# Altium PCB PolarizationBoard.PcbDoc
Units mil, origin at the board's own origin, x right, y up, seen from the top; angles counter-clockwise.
Board outline 2690 x 2935 mil, 2 copper layers (Top Layer, Bottom Layer); 18 components, 12 nets, 69 pads, 11 vias.
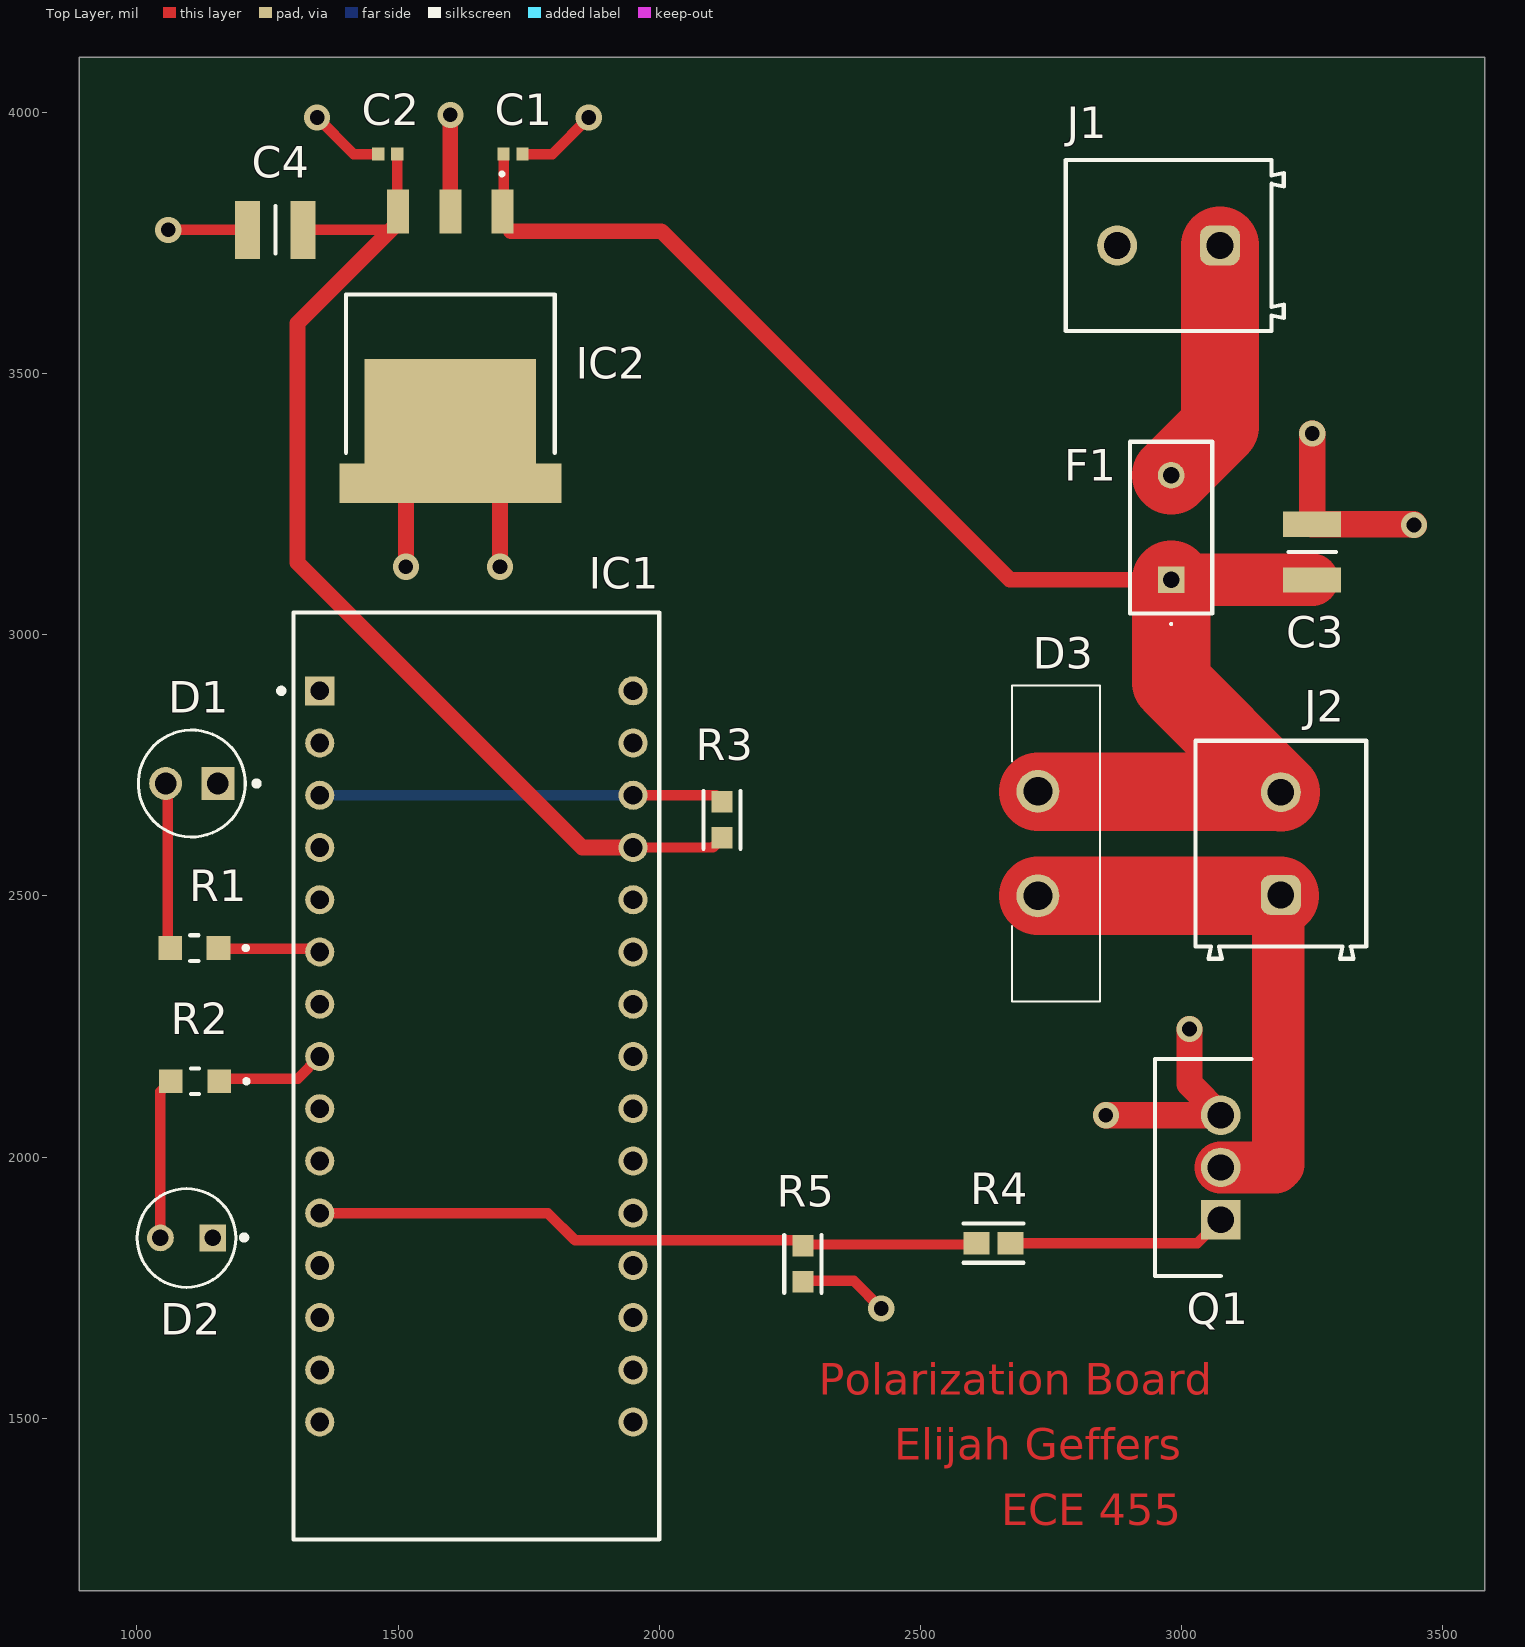
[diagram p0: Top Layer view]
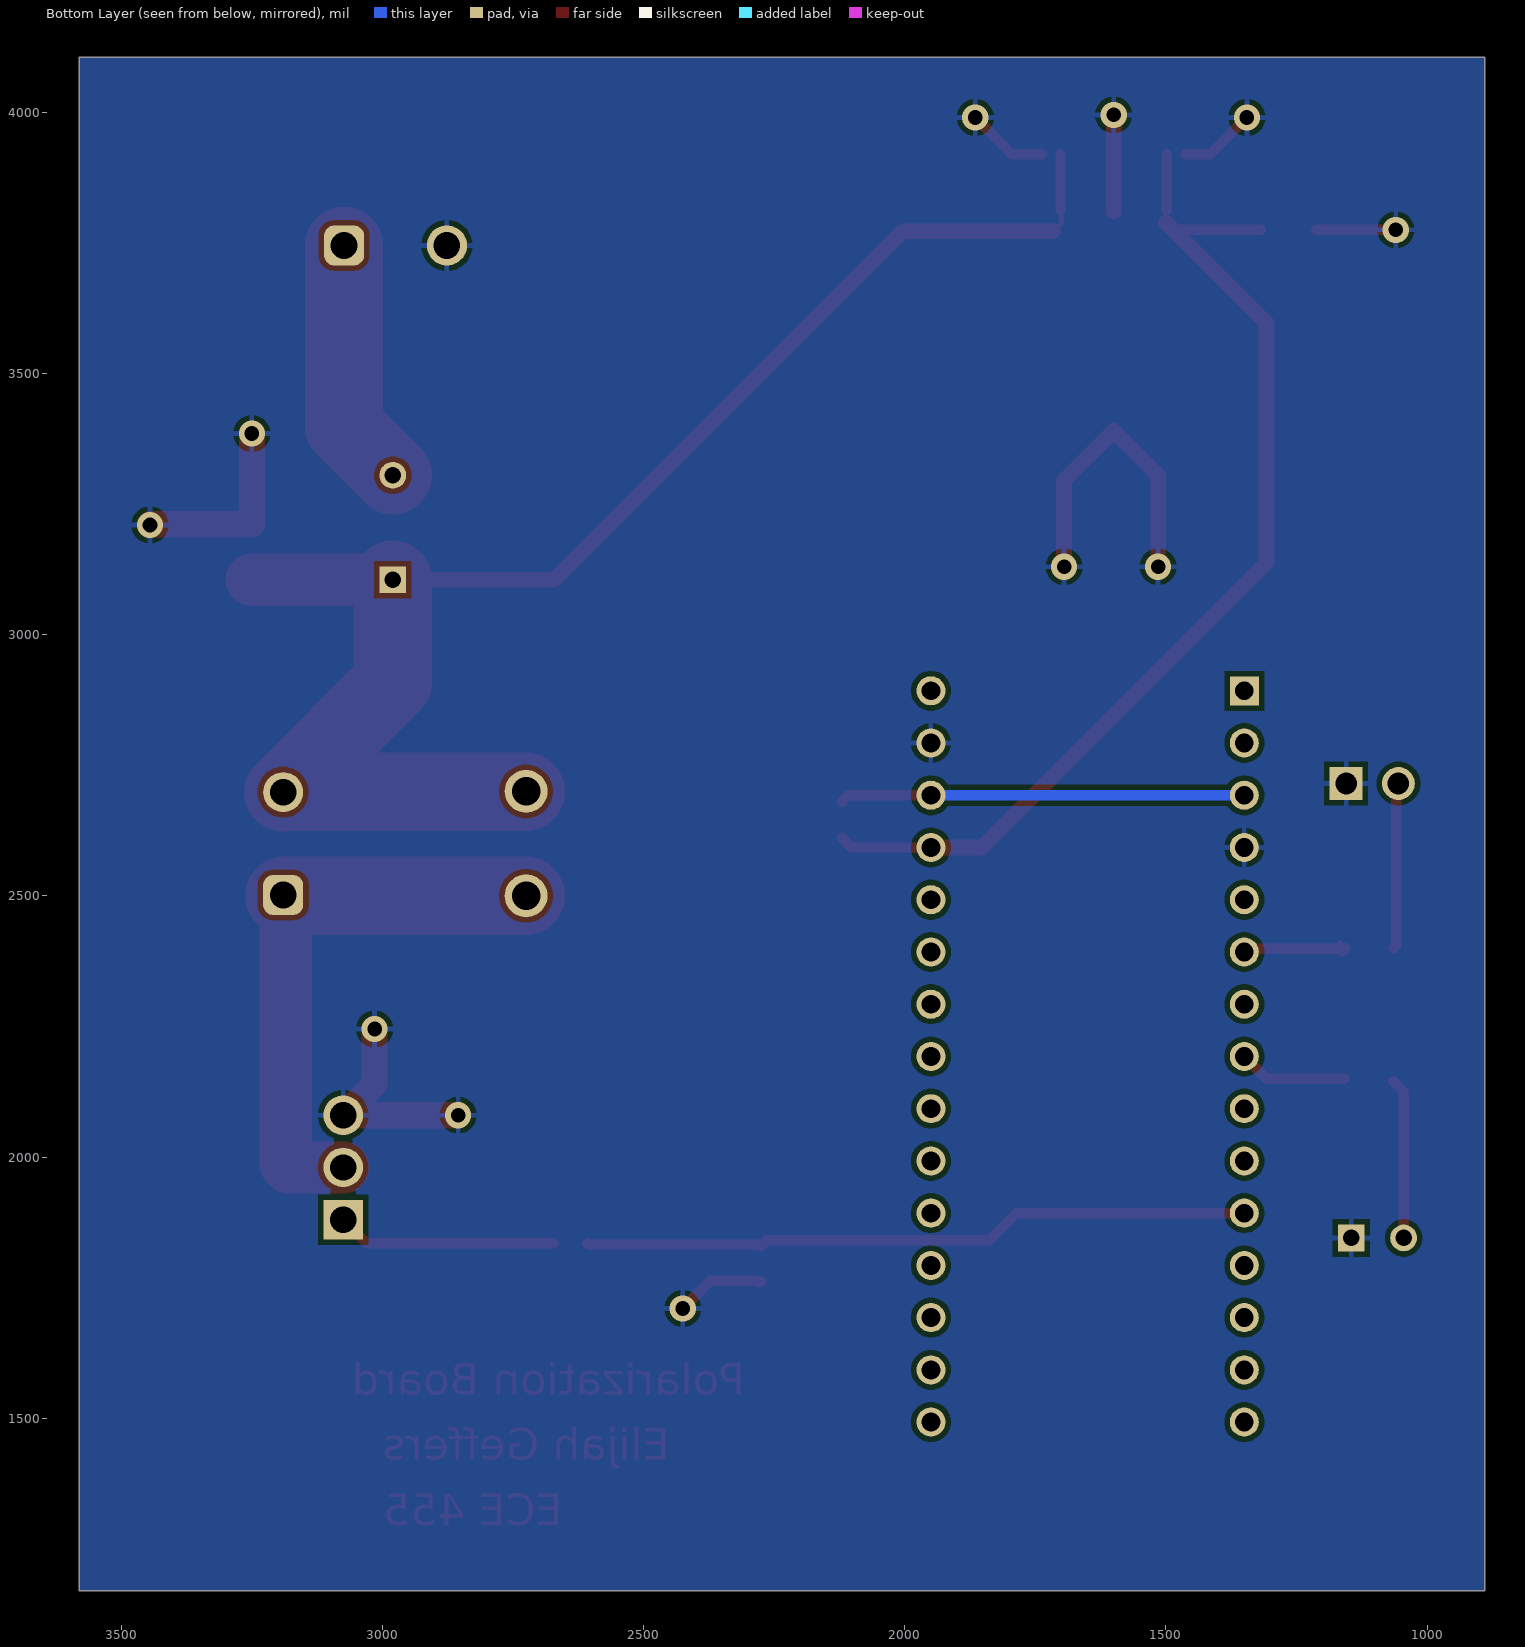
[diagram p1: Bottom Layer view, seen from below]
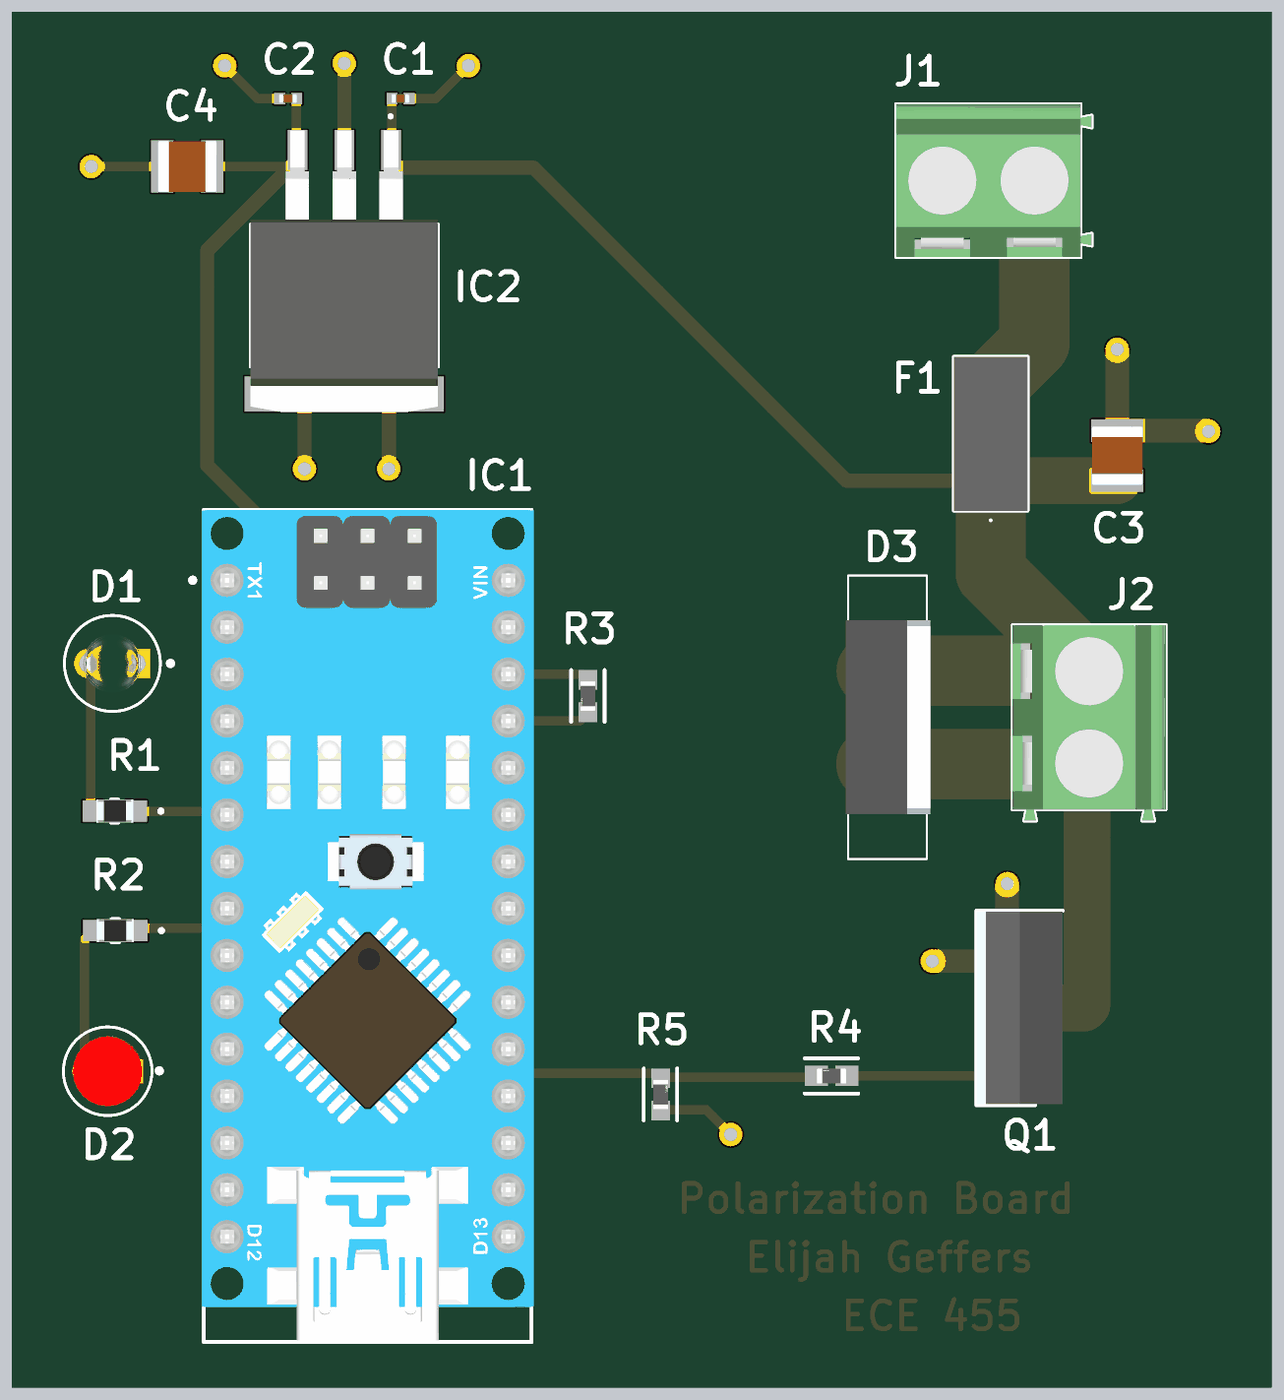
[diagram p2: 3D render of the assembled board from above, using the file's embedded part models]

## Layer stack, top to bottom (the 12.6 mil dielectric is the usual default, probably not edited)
Top Solder: solder mask 0.4, Solder Resist, Dk 3.5
Top Layer: signal copper 1.4
Dielectric 1: dielectric 12.6, FR-4, Dk 4.8
Bottom Layer: signal copper 1.4
Bottom Solder: solder mask 0.4, Solder Resist, Dk 3.5

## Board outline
890,1170 890,4105 3580,4105 3580,1170

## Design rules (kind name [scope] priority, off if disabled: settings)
Clearance [All] p1: gap=10 ignorepadtopadclearanceinfootprint=FALSE
Height [All] p1: minheight=0 maxheight=2000 prefheight=500
PolygonConnect [All] p1: connectstyle=Relief reliefconductorwidth=10 reliefentries=4 polygonreliefangle="90 Angle" airgapwidth=10
RoutingVias [All] p1: holewidth=28 width=50 viastyle="Through Hole" minholewidth=28 minwidth=50 maxholewidth=28 maxwidth=50
SolderMaskExpansion [All] p1: expansion=4 istentingtop=FALSE
SupplyNets "Schematic Supply Nets" [InNet('GND')] p1: voltage=0.000
Width [All] p1: maxlimit=300 minlimit=10 preferedwidth=10 bottomlayer_maxwidth=50 minimp=50.000000 maximp=50.000000 favimp=50.000000
29 further rules are at their usual default settings.

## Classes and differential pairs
component class PolarizationBoard: C1 C2 C3 C4 D1 D2 D3 F1 IC1 IC2 J1 J2 Q1 R1 R2 R3 R5

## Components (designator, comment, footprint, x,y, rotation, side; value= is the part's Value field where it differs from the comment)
C1 "0.22uF" CAPC1005X55N 1720,3920 r0 top
C2 "0.1uF" CAPC1005X55N 1480,3920 r180 top
C3 "10uF" CAPC3225X280N 3250,3158.15 r90 top
C4 "10uF" CAPC3225X280N 1265,3775 r0 top
D1 "LED" FP-6_544-5255_01-4-MFG 1105,2715 r180 top
D2 "LED" FP-LTL-1CHEE-MFG 1095,1845 r180 top
D3 "MBR1045" MBR1045 2712.8,2600 r270 top
F1 "15A" 0697H915002 2980,3105 r90 top
IC1 "A000005" FP-A000005-MFG 1650,2155 r0 top
IC2 "LM7805SX/NOPB" KTT0003B 1600,3311.26 r90 top
J1 "+12V" 691213710002 2975,3745 r180 top
J2 "SENSOR COIL" 691213710002 3190,2600 r90 top
Q1 "IRLZ44NPBF" TO254P469X1042X1967-3P 3075,1880 r90 top
R1 "1.5k" ERA6AEB101V 1110,2400 r180 top
R2 "1.5k" ERA6AEB101V 1111.26,2145 r180 top
R3 "10k" FP-AC0603-IPC_A 2120,2645.48 r270 top
R4 "150" FP-RG1608-IPC_A 2640,1835 r180 top
R5 "10k" FP-AC0603-IPC_A 2275,1795.48 r90 top

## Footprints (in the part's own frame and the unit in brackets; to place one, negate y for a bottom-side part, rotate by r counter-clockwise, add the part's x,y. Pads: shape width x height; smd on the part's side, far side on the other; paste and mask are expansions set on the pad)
0697H915002 [mm]
  rect 1.3x1.3 hole 0.8: 1(0,0)
  round 1.3 hole 0.8: 2(5.08,0)
  silkscreen extent -2.2,-2 6.72,2, body extent -1.64,-2 6.72,2, height 8.2
691213710002 [mm] "5,00mm - modular - green - Horizontal entry with rising cage clamp -  10,0mm height - 02p"
  rrect50% 1.95x1.95 hole 1.3: 1(-2.5,0)
  round 1.95 hole 1.3: 2(2.5,0)
  silkscreen extent -5.6,-4.15 5,4.15, body extent -5.6,-4.15 5,4.15, height 10.05
CAPC1005X55N [mm]
  rect 0.6x0.62 smd: 1(-0.46,0) 2(0.46,0)
  body extent -0.5,-0.25 0.5,0.25, height 0.55
CAPC3225X280N [mm]
  rect 1.22x2.82 smd: 1(-1.35,0) 2(1.35,0)
  silkscreen extent 0,-1.15 0,1.15, body extent -1.6,-1.4 1.6,1.4, height 2.5
ERA6AEB101V [mm]
  rect 1.15x1.15 smd: 1(-1.175,0) 2(1.175,0)
  silkscreen extent -2.6,-0.63 0.2,0.63, body extent -1,-0.63 1,0.63, height 0.5
FP-6_544-5255_01-4-MFG [mm]
  rect 1.6x1.6 hole 1.05 paste-2539.97 mask+0: 1(-1.27,0)
  round 1.6 hole 1.05 paste-2539.97 mask+0: 2(1.27,0)
  silkscreen extent -3.27,-2.6 2.6,2.6, body extent -2.32,-2.32 2.32,2.32, height 0.25
FP-A000005-MFG [mil]
  rect 55.67x55.67 hole 35.98 paste-99999 mask+0: 1(-300,737.5)
  round 55.67 hole 35.98 paste-99999 mask+0: 2(-300,637.5) 3(-300,537.5) 4(-300,437.5) 5(-300,337.5) 6(-300,237.5) 7(-300,137.5) 8(-300,37.5) 9(-300,-62.5) 10(-300,-162.5) 11(-300,-262.5) 12(-300,-362.5) 13(-300,-462.5) 14(-300,-562.5) 15(-300,-662.5) 16(300,-662.5) 17(300,-562.5) 18(300,-462.5) 19(300,-362.5) 20(300,-262.5) 21(300,-162.5) 22(300,-62.5) 23(300,37.5) 24(300,137.5) 25(300,237.5) 26(300,337.5) 27(300,437.5) 28(300,537.5) 29(300,637.5) 30(300,737.5)
  silkscreen extent -379,-888 350,888, body extent -354,-891 354,891, height 10
FP-AC0603-IPC_A [mil]
  rect 41.68x39.85 smd paste+0 mask+0: 1(-34.52,0) 2(34.52,0)
  silkscreen extent -55,-36 55,36, body extent -75,-40 75,40, height 10
FP-LTL-1CHEE-MFG [mm]
  rect 1.3x1.3 hole 0.8 paste-2539.97 mask+0: 1(-1.27,0)
  round 1.3 hole 0.8 paste-2539.97 mask+0: 2(1.27,0)
  silkscreen extent -2.93,-2.4 2.4,2.4, body extent -2.15,-2.15 2.15,2.15, height 0.25
FP-RG1608-IPC_A [mil]
  rect 49.41x43.55 smd paste+0 mask+0: 1(-32.51,0) 2(32.51,0)
  silkscreen extent -57,-38 57,38, body extent -77,-41 77,41, height 10
KTT0003B [mm]
  rect 2.16x1.07 smd: 1(12.67,-2.54) 2(12.67,0) 3(12.67,2.54)
  rect 7x8.33 smd: 4(2,0)
  rect 1.91x1.235 smd: 5(-0.545,4.782) 6(-0.545,-4.782)
  silkscreen extent 0.94,-5.08 14.56,5.08, body extent -1.52,-5.08 13.72,5.08, height 4.54
MBR1045 [mm]
  round 2.085 hole 1.39: 1(-2.54,0.31) 2(2.54,0.31)
  silkscreen extent -7.68,-0.95 7.68,3.32, body extent -5.25,-1.07 5.25,3.52, height 28.86
TO254P469X1042X1967-3P [mm]
  rect 1.92x1.92 hole 1.28: 1(0,0)
  round 1.92 hole 1.28: 2(2.54,0) 3(5.08,0)
  silkscreen extent -2.73,-1.5 7.81,3.19, body extent -2.67,-1.5 7.75,3.19, height 18.84

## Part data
C1: library part MLASU105SB5224KFNA01, "MLASU105SB5224KFNA01", Manufacturer_Name="TAIYO YUDEN"
C2: library part MCASU105SB5104MFNA01, "MCASU105SB5104MFNA01", Manufacturer_Name="TAIYO YUDEN"
C3 C4: library part MCASU32MAB7106KPNA1J, "MCASU32MAB7106KPNA1J", Manufacturer_Name="TAIYO YUDEN", Mouser Part Number=963-U32MAB7106KPNA1J
D1: library part CMP-00030-55433990-1, "TLLG4400 (G)", Case/Package=T, Color=Green, Forward Current=2mA, Forward Voltage=1.9V, Max Operating Temperature=100°C, Max Power Dissipation=20mW, Min Operating Temperature=-40°C, Reverse Voltage=20V, Voltage Rating (DC)=2.4V
D2: library part CMP-22017-000040-1, "LTL-1CHEE (R)", Case/Package=T, Color=Red, Forward Current=30mA, Forward Voltage=2V, Max Operating Temperature=100°C, Max Power Dissipation=100mW, Min Operating Temperature=-55°C, Package Quantity=1000, Reverse Voltage=5V, Test Current=10mA
D3: "Schottky Diode", Manufacturer_Name=onsemi, Mouser Part Number=512-MBR1045
F1: library part 0697H9150-02, "0697H9150-02", Manufacturer_Name=BelFuse, Mouser Part Number=530-0697H9150-02
IC1: library part CMP-189986-000002-1, "ARDUINO NANO ATMEGA328 EVAL BRD", Operating Supply Voltage=12V, Package Quantity=50
IC2: library part LM7805SX_NOPB, "Integrated Circuit", Manufacturer_Name="Texas Instruments", Mouser Part Number=595-LM7805SX/NOPB
J1 J2: library part CMP-1502-02526-3, "691213710002", Color=Green, Current=10A, Max Operating Temperature=105°C, Min Operating Temperature=-40°C, Voltage=300V
Q1: "MOSFET (N-Channel)", Manufacturer_Name=Infineon, Mouser Part Number=942-IRLZ44NPBF
R1 R2: library part ERA-6AED152V, "ERA-6AED152V", Manufacturer_Name=Panasonic, Mouser Part Number=667-ERA-6AED152V
R3 R5: library part CMP-03412-040683-1, "AC0603JR-7W10KL"
R4: library part CMP-28537-000042-1, "RG1608N-151-W-T5", Case Code (Imperial)=0603, Case Code (Metric)=1608, Max Operating Temperature=155°C, Max Power Dissipation=100mW, Min Operating Temperature=-55°C, Package Quantity=5000, Power Rating=62.5mW, Resistance=150R, Resistor Type="Thin Film", Temperature Coefficient=10ppm/°C, Tolerance=0.05%, Voltage Rating=75V

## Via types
v1: diameter 50, hole 28, Top Layer to Bottom Layer, 11 vias

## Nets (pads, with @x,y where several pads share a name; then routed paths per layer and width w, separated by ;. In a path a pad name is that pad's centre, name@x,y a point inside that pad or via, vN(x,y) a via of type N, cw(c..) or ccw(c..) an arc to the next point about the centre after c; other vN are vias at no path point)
GND: C1.2 C2.2 C3.2 C4.1 D1.1 D2.1 IC1.4 IC1.29 IC2.2 IC2.4 J1.2 Q1.3 R5.1 | length 2185
  Top Layer w20: v1(1060,3775) C4.1 ; v1(1345,3990) 1415,3920 C2.2 ; C1.2 1795,3920 v1(1865,3990) ; R5.1 2282.91,1760.97 2284.92,1762.98 2372.02,1762.98 v1(2425,1710)
  Top Layer w30: v1(1515,3130) 1515,3305 IC2.4 1695,3295 v1(1695,3130) ; IC2.2 v1(1600,3995)
  Top Layer w50: v1(2855,2080) Q1.3 3015,2140 v1(3015,2245) ; v1(3250,3385) C3.2 3443.7,3211.3 v1(3445,3210)
NetC1_1: C1.1 C3.1 D3.1 F1.1 IC2.1 J2.2 | length 2923.4
  Top Layer w10: IC2.1@1701.89,3811.97 IC2.1 1700,3788.62 IC2.1@1716.06,3772.56 ; D3.1 D3.1@2725.79,2699.21
  Top Layer w20: IC2.1@1701.89,3811.97 C1.1
  Top Layer w30: IC2.1@1716.06,3772.56 2003.96,3772.56 2671.52,3105 F1.1
  Top Layer w100: F1.1 C3.1
  Top Layer w150: D3.1@2725.79,2699.21 J2.2@3189.21,2699.21 ; F1.1 2980,2908.43 J2.2
NetC2_1: C2.1 C4.2 IC1.27 IC2.3 R3.2 | length 2057.2
  Top Layer w10: IC2.3@1498.11,3811.97 IC2.3 ; IC2.3@1500,3788.62 IC2.3@1500,3791.06 ; R3.2 R3.2@2120,2611.89
  Top Layer w20: C4.2 IC2.3@1483.94,3775 ; IC2.3@1498.11,3811.97 C2.1 ; IC1.27 2102.45,2592.5 2120,2610.05 R3.2
  Top Layer w30: IC2.3@1500,3788.62 1307.4,3596.02 1307.4,3137.6 1852.5,2592.5 IC1.27
NetD1_2: D1.2 R1.2 | length 332.8
  Top Layer w10: R1.2@1053.74,2410 R1.2
  Top Layer w20: D1.2 1059.37,2710.63 1059.37,2404.37 R1.2
NetD2_2: D2.2 R2.2 | length 308.3
  Top Layer w20: D2.2 1045,2125 R2.2
NetD3_2: D3.2 J2.1 Q1.2 | length 1093.6
  Top Layer w10: 3179.14,1980 3185,1985.86 ; J2.1@3185,2496.57 J2.1
  Top Layer w100: Q1.2 3179.14,1980 ; 3185,1985.86 J2.1@3185,2496.57
  Top Layer w150: D3.2 J2.1@3188.43,2500
NetF1_2: F1.2 J1.1 | length 478.7
  Top Layer w150: F1.2 3073.43,3398.43 J1.1
NetIC1_3: IC1.3 IC1.28 R3.1 | length 775.7
  Top Layer w20: IC1.28 2108.42,2692.5 2120,2680.92 R3.1
  Bottom Layer w20: IC1.3 IC1.28
NetIC1_6: IC1.6 R1.1 | length 219.3
  Top Layer w10: R1.1 R1.1@1166.26,2410
  Top Layer w20: R1.1@1156.26,2398.75 R1.1@1157.51,2398.75 ; R1.1 R1.1@1157.51,2398.75 ; R1.1@1162.51,2393.75 R1.1@1157.51,2398.75 ; IC1.6 1343.75,2398.75 R1.1@1157.51,2398.75
NetIC1_8: IC1.8 R2.1 | length 210.1
  Top Layer w20: R2.1@1157.52,2150 1307.5,2150 IC1.8
NetIC1_11: IC1.11 R4.2 R5.2 | length 1285.7
  Top Layer w20: IC1.11 1786.53,1892.5 1838.7,1840.33 2265.08,1840.33 2275,1830.41 R5.2 2277.5,1832.5 2604.99,1832.5 R4.2
NetQ1_1: Q1.1 R4.1 | length 452.3
  Top Layer w10: R4.1 R4.1@2675.43,1835 ; Q1.1@3055,1860 Q1.1
  Top Layer w20: R4.1 3030,1835 Q1.1
pads on no net: IC1.1 IC1.2 IC1.5 IC1.7 IC1.9 IC1.10 IC1.12 IC1.13 IC1.14 IC1.15 IC1.16 IC1.17 IC1.18 IC1.19 IC1.20 IC1.21 IC1.22 IC1.23 IC1.24 IC1.25 IC1.26 IC1.30 IC2.5 IC2.6

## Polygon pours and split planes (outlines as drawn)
GND on Bottom Layer "NONET_L02_P-001" (solid, pour order 0): 890,4105 3580,4105 3580,1170 890,1170

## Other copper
Top Layer:
  text "Polarization Board" at 2305,1545 h60
  text "Elijah Geffers" at 2450,1419.99 h60
  text "ECE 455" at 2655,1295 h60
